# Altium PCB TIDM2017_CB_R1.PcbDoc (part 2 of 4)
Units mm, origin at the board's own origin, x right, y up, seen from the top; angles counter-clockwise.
Board outline 120 x 77 mm, 4 copper layers (Top Layer, Layer 1, Layer 2, Bottom Layer), stack 1.856 mm thick; 246 components, 167 nets, 1255 pads, 326 vias.
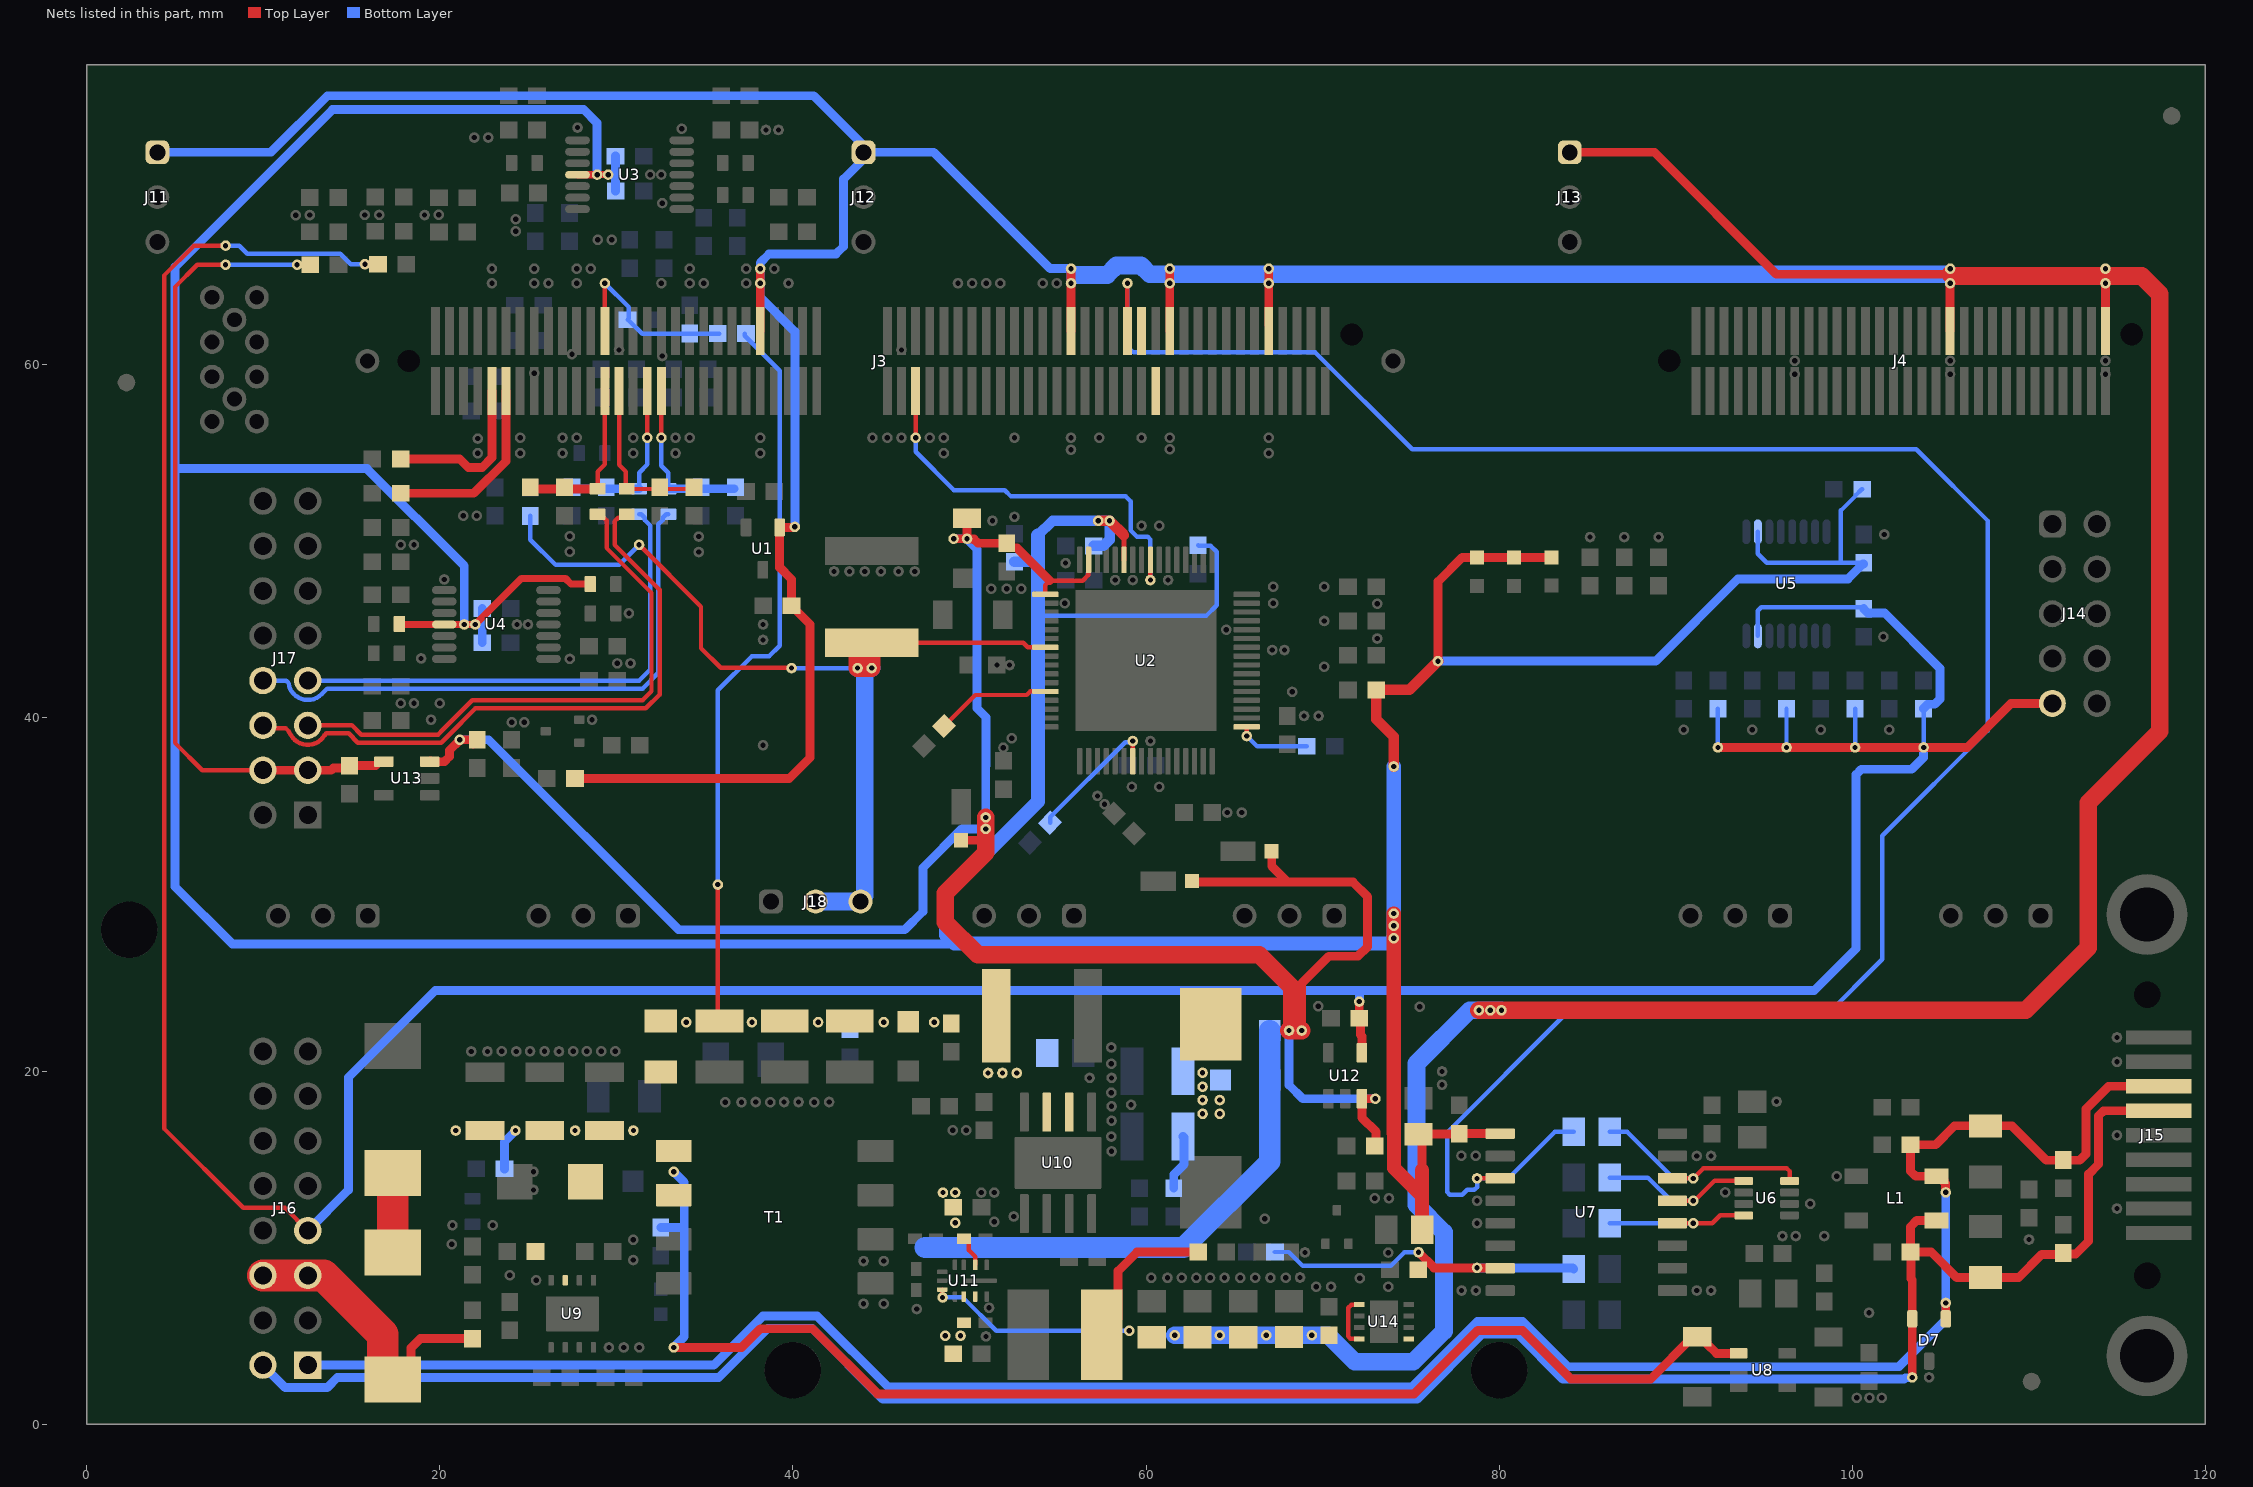
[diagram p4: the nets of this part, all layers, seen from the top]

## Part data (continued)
C24 C26 C28: library part CMP-0083626-1, "CAP, CERM, 0.1 µF, 16 V,+/- 10%, X7R, AEC-Q200 Grade 1, 0603", Cap_Case=0603, Manufacturer=AVX, Supplier Part Number 1=478-9382-1-ND, TempCo=X7R, Tolerance_%=10%, Value2=16V, ValueDisplayed=0.1µF
C29 C31: library part CMP-0007280-4, "CAP, CERM, 68 pF, 100 V, +/- 5%, C0G/NP0, 0603", Cap_Case=0603, Manufacturer=MuRata, Supplier Part Number 1=490-1347-1-ND, TempCo=C0G/NP0, Tolerance_%=5%, Value1=Unknown, Value2=100V, ValueDisplayed=68pF
C30: library part CMP-0007146-4, "CAP, CERM, 4700 pF, 50 V, +/- 10%, X7R, AEC-Q200 Grade 1, 0603", Cap_Case=0603, Manufacturer=MuRata, Supplier Part Number 1=490-4932-1-ND, TempCo=X7R, Tolerance_%=10%, Value1=Unknown, Value2=50V, ValueDisplayed=4700pF
C36 C46: library part CMP-0007255-4, "CAP, CERM, 22 pF, 100 V, +/- 5%, C0G/NP0, 0603", Cap_Case=0603, Manufacturer=MuRata, Supplier Part Number 1=490-1335-1-ND, TempCo=C0G/NP0, Tolerance_%=5%, Value1=Unknown, Value2=100V, ValueDisplayed=22pF
C37 C38 C39 C51 C52: library part CMP-0080552-1, "CAP, CERM, 22 µF, 25 V,+/- 10%, X7R, AEC-Q200 Grade 1, 1210", Cap_Case=1210, Manufacturer="Taiyo Yuden", Supplier Part Number 1=587-5949-1-ND, TempCo=X7R, Tolerance_%=10%, Value2=25V, ValueDisplayed=22µF
C40 C50 C67 C73: library part CMP-0079602-1, "CAP, CERM, 0.1 µF, 50 V,+/- 10%, X7R, AEC-Q200 Grade 1, 0603", Cap_Case=0603, Manufacturer=Kemet, Supplier Part Number 1=399-6856-1-ND, TempCo=X7R, Tolerance_%=10%, Value2=50V, ValueDisplayed=0.1µF
C41 C45: library part CMP-0007079-4, "CAP, CERM, 0.047 uF, 50 V, +/- 10%, X7R, AEC-Q200 Grade 1, 0603", Cap_Case=0603, Manufacturer=TDK, Supplier Part Number 1=445-5664-1-ND, TempCo=X7R, Tolerance_%=10%, Value1="0.049007 ohm", Value2=50V, ValueDisplayed=0.047uF
C42 C43 C44: library part CMP-0009164-2, "CAP, CERM, 10 uF, 50 V, +/- 10%, X7S, AEC-Q200 Grade 1, 1210", Cap_Case=1210_280, Manufacturer=TDK, Supplier Part Number 1=445-7004-1-ND, TempCo=X7S, Tolerance_%=10%, Value1="0.002827 ohm", Value2=50V, ValueDisplayed=10uF
C47: library part CMP-0006861-4, "CAP, CERM, 0.1 uF, 50 V, +/- 10%, X7R, 0603", Cap_Case=0603, Manufacturer=Kemet, Supplier Part Number 1=399-5089-1-ND, TempCo=X7R, Tolerance_%=10%, Value1=Unknown, Value2=50V, ValueDisplayed=0.1uF
C48: library part CMP-0008572-2, "CAP, CERM, 1000 pF, 2000 V, +/- 10%, X7R, 1206_190", Cap_Case=1206, Manufacturer="Johanson Technology", TempCo=X7R, Tolerance_%=10%, Value1=Unknown, Value2=2000V, ValueDisplayed=1000pF
C49: library part CMP-0007141-3, "CAP, CERM, 0.047 uF, 25 V, +/- 10%, X7R, AEC-Q200 Grade 1, 0603", Cap_Case=0603, Manufacturer=MuRata, Supplier Part Number 1=490-8018-1-ND, TempCo=X7R, Tolerance_%=10%, Value1=Unknown, Value2=25V, ValueDisplayed=0.047uF
C57: library part CMP-0860440-1, "CAP, CERM, 0.1 µF, 100 V,+/- 10%, X7R, AEC-Q200 Grade 1, 0805", Cap_Case=0805, Manufacturer=MuRata, TempCo=X7R, Tolerance_%=10%, Value2=100V, ValueDisplayed=0.1µF
C59 C66: library part CMP-0085644-1, "CAP, CERM, 10 µF, 16 V,+/- 20%, X6S, AEC-Q200 Grade 2, 0603", Cap_Case=0603, Manufacturer=MuRata, TempCo=X6S, Tolerance_%=20%, Value2=16V, ValueDisplayed=10µF
C60 C61 C62 C63 C72: library part CMP-0084680-1, "CAP, CERM, 22 µF, 25 V,+/- 20%, X5R, AEC-Q200 Grade 3, 0805", Cap_Case=0805, Manufacturer=MuRata, TempCo=X5R, Tolerance_%=20%, Value2=25V, ValueDisplayed=22µF
C64 C68: library part CMP-0079154-1, "CAP, CERM, 1 µF, 16 V,+/- 10%, X7R, AEC-Q200 Grade 1, 0603", Cap_Case=0603, Manufacturer=MuRata, Supplier Part Number 1=490-12657-1-ND, TempCo=X7R, Tolerance_%=10%, Value2=16V, ValueDisplayed=1µF
C65 C69 C70 C71: library part CMP-0084284-1, "CAP, CERM, 2.2 µF, 10 V,+/- 10%, X7R, AEC-Q200 Grade 1, 0603", Cap_Case=0603, Manufacturer=MuRata, TempCo=X7R, Tolerance_%=10%, Value2=10V, ValueDisplayed=2.2µF
C74 C75: library part CMP-0078265-1, "CAP, CERM, 0.22 µF, 16 V,+/- 10%, X7R, AEC-Q200 Grade 1, 0402", Cap_Case=0402, Manufacturer=MuRata, Supplier Part Number 1=490-10671-1-ND, TempCo=X7R, Tolerance_%=10%, Value2=16V, ValueDisplayed=0.22µF
C96: library part CMP-0750099-1, "CAP, CERM, 1 µF, 35 V,+/- 10%, X5R, AEC-Q200 Grade 3, 0402", Cap_Case=0402, Manufacturer=MuRata, TempCo=X5R, Tolerance_%=10%, Value2=35V, ValueDisplayed=1µF
D1 D3: library part CMP-0002905-2, "LED, Green, SMD", Color=Green, Manufacturer="Wurth Elektronik", Value1=W, Value2=3.2V
D2: library part CMP-0002947-3, "LED, Red, SMD", Color=Red, Manufacturer="Wurth Elektronik", Power_TotalModule=72mW, Value1=0.072W, Value2=2V
D4 D5 D6: library part CMP-0080709-2, "Diode, Schottky, 20 V, 2 A, AEC-Q101, PowerDI323", Manufacturer="Diodes Inc.", Value1=2A, Value2=0.47V
D7: library part CMP-0005928-2, "Diode, TVS, Bi, 7 V, SOT-23", Manufacturer=Bourns, Value1=400W
D8 D10 D13 D14: library part CMP-0085903-1, "Diode, Schottky, 60 V, 3 A, AEC-Q101, SOD-123W", Manufacturer=Nexperia, Value1=3A, Value2=0.62V
D9: library part CMP-0077075-2, "Diode, Schottky, 100 V, 3 A, AEC-Q101, SMC", Manufacturer=Vishay-Siliconix, Value1=3A, Value2=0.8V
D11: library part CMP-0005729-4, "Diode, TVS, Uni, 26 V, 42.1 Vc, AEC-Q101, SMC", Manufacturer=Littelfuse, Value1=3000W
D12: library part CMP-0005514-4, "Diode, Zener, 27 V, 3 W, SMA", Manufacturer="Micro Commercial Components", Power_W=3W
FID1 FID2 FID3: library part CMP-0077181-1, "Fiducial mark.  There is nothing to buy or mount.", Manufacturer=N/A
J1 J2: library part CMP-0055255-2, "MMCX JACK, 50 Ohm, Gold, TH", Color=Gold, Manufacturer=Molex, Supplier Part Number 1=WM5557-ND
J3: library part CMP-0003814-2, "C2000 controlCARD-120HSEC connector, SMT", Manufacturer=Samtec
J4: library part CMP-0003859-2, "C2000 controlCARD-180HSEC (60-pin addon) connector, SMT", Manufacturer=Samtec
J5 J6 J7 J8 J9 J10 J11 J12 J13 J18: library part CMP-0076709-1, "Receptacle, 2.54mm, 3x1, Gold, TH", Color=Black, Manufacturer=Mill-Max, Supplier Part Number 1=575-8014100310001000
J14: library part CMP-0860034-1, "Header, 2.54mm, 5x2, Gold, TH", Color=Black, Manufacturer=Samtec
J15: library part CMP-0074875-1, "Receptacle, D-Sub, 9 Position, R/A, SMT", Color=Black, Manufacturer=NorComp, Supplier Part Number 1=190-09FA-ND
J16 J17: library part CMP-0075673-1, "Header (Shrouded), 2.54mm, 8x2, Tin, R/A, TH", Color=Black, Manufacturer=Samtec, Supplier Part Number 1=TSS-108-04-L-D-RA-ND
L1: library part CMP-0076845-1, "Coupled inductor, 51 µH, 0.2 A, 1 ohm, AEC-Q200 Grade 0, SMD", Manufacturer=TDK, Supplier Part Number 1=445-3958-1-ND, ValueDisplayed=51µH
L2: library part CMP-0079799-1, "Inductor, Shielded, 68 µH, 2 A, 0.24 ohm, AEC-Q200 Grade 1, SMD", Manufacturer="Pulse Engineering", Supplier Part Number 1=553-3443-1-ND, Value1="0.24 ohm", Value2=2A, ValueDisplayed=68µH
L3: library part CMP-0056765-1, "Inductor, Shielded, Ferrite, 10 uH, 3.2 A, 0.0624 ohm, AEC-Q200 Grade 1, SMD", Manufacturer=Bourns, Supplier Part Number 1=SRN6045TA-100MCT-ND, Value1="0.0624 ohm", Value2=3.2A, ValueDisplayed=10uH
LBL1: library part CMP-0003625-1, "Thermal Transfer Printable Labels, 0.650\" W x 0.200\" H - 10,000 per roll", Manufacturer=Brady, Supplier Part Number 1=97C5133
Logo1: library part CMP-0074838-1, "Texas Instrument Corporate Signature"
Logo2: library part CMP-0074844-1
Logo3: library part CMP-0074847-1, "FCC_disclaimer"
Logo4: library part CMP-0074769-1
Q1 Q2: library part CMP-0000791-1, "MOSFET, N-CH, 60 V, 0.28 A, AEC-Q101, SOT-323", Alternate Manufacturer=None, Manufacturer="Infineon Technologies", Supplier Part Number 1=BSS138WH6327XTSA1CT-ND, Value2="1 nC"
R1 R4: library part CMP-0081280-1, "RES, 47.0, 1%, 0.1 W, AEC-Q200 Grade 0, 0603", Manufacturer=Vishay-Dale, Power_W=100mW, Supplier Part Number 1=541-47.0HCT-ND, TempCo="100 ppm/C", Tolerance_%=1%, Value2=0.1W, Value_Code=47R0, ValueDisplayed=47.0
R2 R5: library part CMP-0022455-4, "RES, 4.64 k, 1%, 0.1 W, AEC-Q200 Grade 0, 0603", Manufacturer=Vishay-Dale, Power_W=100mW, Supplier Part Number 1=541-4.64KHCT-ND, TempCo="100 ppm/C", Tolerance_%=1%, Value2=0.1W, Value_Code=4k64, ValueDisplayed=4.64k
R3: library part CMP-0022115-4, "RES, 1.15 k, 1%, 0.1 W, AEC-Q200 Grade 0, 0603", Manufacturer=Vishay-Dale, Power_W=100mW, Supplier Part Number 1=541-1.15KHCT-ND, TempCo="100 ppm/C", Tolerance_%=1%, Value2=0.1W, Value_Code=1k15, ValueDisplayed=1.15k
R6 R9 R15 R30 R31 R67 R81: library part CMP-0023168-5, "RES, 51.1, 1%, 0.1 W, 0603", Manufacturer=Yageo, Power_W=100mW, Supplier Part Number 1=311-51.1HRCT-ND, TempCo="100 ppm/C", Tolerance_%=1%, Value2=0.1W, Value_Code=51R1, ValueDisplayed=51.1
R7 R12 R70 R72: library part CMP-0023837-2, "RES, 18.4 k, 0.1%, 0.1 W, 0603", Manufacturer="Yageo America", Power_W=100mW, TempCo="25 ppm/C", Tolerance_%=0.1%, Value2=0.1W, Value_Code=18k4, ValueDisplayed=18.4k
R8 R29 R32 R56 R66 R69 R71 R73 R76 R78 R82 R84 R86 R87: library part CMP-0022746-5, "RES, 10.0 k, 1%, 0.1 W, 0603", Manufacturer=Yageo, Power_W=100mW, Supplier Part Number 1=311-10.0KHRCT-ND, TempCo="100 ppm/C", Tolerance_%=1%, Value2=0.1W, Value_Code=10k0, ValueDisplayed=10.0k
R10: library part CMP-0025288-2, "RES, 43.7 k, 0.5%, 0.1 W, 0603", Manufacturer="Yageo America", Power_W=100mW, TempCo="50 ppm/C", Tolerance_%=0.5%, Value2=0.1W, Value_Code=43k7, ValueDisplayed=43.7k
R11: library part CMP-0021998-4, "RES, 10.0 k, 1%, 0.1 W, AEC-Q200 Grade 0, 0603", Manufacturer=Vishay-Dale, Power_W=100mW, Supplier Part Number 1=541-10.0KHCT-ND, TempCo="100 ppm/C", Tolerance_%=1%, Value2=0.1W, Value_Code=10k0, ValueDisplayed=10.0k
R13 R28 R39 R55 R68 R74 R75 R77 R79 R80 R83 R85: library part CMP-0088378-2, "6.04 kOhms ±0.1% 0.2W, 1/5W Chip Resistor 0603 (1608 Metric) Automotive AEC-Q200, Pulse Withstanding Thick Film", Digikey Part Number=P20061CT-ND, Manufacturer=Panasonic, Mouser Part Number=667-ERJ-PB3B6041V, Operating Temperature Range="-55°C to +155°C", Power_W=200mW, TempCo=50ppm/°C, Tolerance_%=0.1%
R14 R19 R20 R38 R57: library part CMP-0023385-3, "RES, 100 k, 0.05%, 0.1 W, AEC-Q200 Grade 0, 0603", Manufacturer=Panasonic, Power_W=100mW, Supplier Part Number 1=P100KBECT-ND, TempCo="10 ppm/C", Tolerance_%=0.05%, Value2=0.1W, Value_Code=100k
R16 R17 R18: library part CMP-0024021-2, "RES, 271, 0.1%, 0.1 W, 0603", Manufacturer="Yageo America", Power_W=100mW, TempCo="25 ppm/C", Tolerance_%=0.1%, Value2=0.1W, Value_Code=271R, ValueDisplayed=271
R21 R22 R63 R65: library part CMP-0023341-3, "RES, 10.0 k, 1%, 0.1 W, AEC-Q200 Grade 0, 0603", Manufacturer="Stackpole Electronics Inc", Power_W=100mW, Supplier Part Number 1=RMCF0603FT10K0CT-ND, TempCo="100 ppm/C", Tolerance_%=1%, Value2=0.1W, Value_Code=10k0, ValueDisplayed=10.0k
R23 R24 R25 R26 R27 R62 R64 R88: library part CMP-0022109-5, "RES, 1.00 k, 1%, 0.1 W, AEC-Q200 Grade 0, 0603", Manufacturer=Vishay-Dale, Power_W=100mW, Supplier Part Number 1=541-1.00KHCT-ND, TempCo="100 ppm/C", Tolerance_%=1%, Value2=0.1W, Value_Code=1k00, ValueDisplayed=1.00k
R33: library part CMP-0023343-3, "RES, 0, 1%, 0.1 W, AEC-Q200 Grade 0, 0603", Manufacturer="Stackpole Electronics Inc", Power_W=100mW, Supplier Part Number 1=RMCF0603ZT0R00CT-ND, TempCo=ppm/C, Tolerance_%=1%, Value2=0.1W, Value_Code=0
R34 R37 R40: library part CMP-0086358-1, "RES, 0, 0%, 0.25 W, AEC-Q200 Grade 0, 0603", Manufacturer=Rohm, Power_W=250mW, Tolerance_%=0%, Value2=0.25W, Value_Code=0000, ValueDisplayed=0
R35 R36: library part CMP-0018709-3, "RES, 60, 10%, 0.25 W, AEC-Q200 Grade 0, 1206", Manufacturer=Vishay-Dale, Power_W=250mW, Supplier Part Number 1=CRCW120660R0KNEAIF-ND, TempCo="200 ppm/C", Tolerance_%=10%, Value2=0.25W, Value_Code=60R0, ValueDisplayed=60
R41 R42 R43 R44 R45: library part CMP-0020443-3, "RES, 0, 5%, 0.333 W, AEC-Q200 Grade 0, 0805", Manufacturer=Vishay-Dale, Power_W=333mW, Supplier Part Number 1=541-0.0TBCT-ND, TempCo="200 ppm/C", Tolerance_%=5%, Value2=0.333W, Value_Code=0000, ValueDisplayed=0
R46: library part CMP-0084243-1, "RES, 100, 1%, 0.25 W, AEC-Q200 Grade 0, 0603", Manufacturer=Vishay-Dale, Power_W=250mW, TempCo="100 ppm/C", Tolerance_%=1%, Value2=0.25W, Value_Code=100R, ValueDisplayed=100
R47: library part CMP-0021991-4, "RES, 100, 1%, 0.1 W, AEC-Q200 Grade 0, 0603", Manufacturer=Vishay-Dale, Power_W=100mW, Supplier Part Number 1=541-100HCT-ND, TempCo="100 ppm/C", Tolerance_%=1%, Value2=0.1W, Value_Code=100R, ValueDisplayed=100
R48 R52: library part CMP-0018760-2, "RES, 0, 5%, 0.25 W, AEC-Q200 Grade 0, 1206", Manufacturer=Vishay-Dale, Power_W=250mW, Supplier Part Number 1=541-2239-1-ND, TempCo=ppm/C, Tolerance_%=5%, Value2=0.25W, Value_Code=0000, ValueDisplayed=0
R49 R50: library part CMP-0022244-4, "RES, 261 k, 1%, 0.1 W, AEC-Q200 Grade 0, 0603", Manufacturer=Vishay-Dale, Power_W=100mW, Supplier Part Number 1=541-261KHCT-ND, TempCo="100 ppm/C", Tolerance_%=1%, Value2=0.1W, Value_Code=261k
R51: library part CMP-0022024-4, "RES, 121 k, 1%, 0.1 W, AEC-Q200 Grade 0, 0603", Manufacturer=Vishay-Dale, Power_W=100mW, Supplier Part Number 1=541-121KHCT-ND, TempCo="100 ppm/C", Tolerance_%=1%, Value2=0.1W, Value_Code=121k
R53: library part CMP-0022030-4, "RES, 12.1 k, 1%, 0.1 W, AEC-Q200 Grade 0, 0603", Manufacturer=Vishay-Dale, Power_W=100mW, Supplier Part Number 1=541-12.1KHCT-ND, TempCo="100 ppm/C", Tolerance_%=1%, Value2=0.1W, Value_Code=12k1, ValueDisplayed=12.1k
R54: library part CMP-0022544-4, "RES, 64.9 k, 1%, 0.1 W, AEC-Q200 Grade 0, 0603", Manufacturer=Vishay-Dale, Power_W=100mW, Supplier Part Number 1=541-64.9KHCT-ND, TempCo="100 ppm/C", Tolerance_%=1%, Value2=0.1W, Value_Code=64k9, ValueDisplayed=64.9k
R58: library part CMP-0031885-1, "97.6 kOhms ±0.5% 0.2W, 1/5W Chip Resistor 0603 (1608 Metric) Automotive AEC-Q200, Pulse Withstanding Thick Film", Digikey Part Number=P20510CT-ND, Manufacturer=Panasonic, Mouser Part Number=667-ERJ-PB3D9762V, Operating Temperature Range="-55°C to +155°C", Power_W=200mW, TempCo=50ppm/°C, Tolerance_%=0.5%
R59: library part CMP-0022665-4, "RES, 9.09 k, 1%, 0.1 W, AEC-Q200 Grade 0, 0603", Manufacturer=Vishay-Dale, Power_W=100mW, Supplier Part Number 1=541-9.09KHCT-ND, TempCo="100 ppm/C", Tolerance_%=1%, Value2=0.1W, Value_Code=9k09, ValueDisplayed=9.09k
T1: library part CMP-0088070-1, "FLYBACK TRANSFORMER", Manufacturer=Coilcraft
U1: library part CMP-0079649-1, "Automotive 20 ppm / degC Max, 100 uA, SOT23-3 Series Voltage Reference, DBZ0003A (SOT-23-3)", Alternate Manufacturer="Texas Instruments", Alternate PartNumber=REF3133AQDBZTQ1
U2: library part CMP-0089128-1, "3-Phase 48-V Automotive Gate Driver Unit (GDU) with Advanced Protection and Diagnostics", Manufacturer="Texas Instruments", Max Supply Voltage=15V, Min Supply Voltage=3V, Nominal Supply Current=15-24mA, Operating Temperature Range="-40°C to +175°C"
U3 U4: library part CMP-0082283-1, "4 channel, 10-MHz, Low-Noise, RRIO, CMOS Operational Amplifier for Cost-Sensitive Systems, PW0014A (TSSOP-14)", Alternate Manufacturer="Texas Instruments", Alternate PartNumber=TLV9064IPWT, Operating Temperature Range="-40 to 125 C", Rating=Catalog
U5: library part CMP-0067443-1, "6-Bit Bidirectional Voltage-Level Translator with Auto Direction Sensing and +/-15-kV ESD Protect, PW0016A (TSSOP-16)", Alternate Manufacturer="Texas Instruments"
U6: library part CMP-0089901-1, "Automotive High Speed CAN Transceiver", Manufacturer="Texas Instruments", Max Supply Voltage=5.5V, Min Supply Voltage=4.5V, Nominal Supply Current=5-180mA, Operating Temperature Range="-40°C to +150°C"
U7: library part CMP-0078446-2, "High Speed, Robust EMC Triple-Channel Digital Isolators, DW0016B (SOIC-16)", Alternate Manufacturer="Texas Instruments", Alternate PartNumber=ISO7731DW, Operating Temperature Range="-55 to 125 C", Rating=Catalog
U8: library part CMP-0077329-2, "Automotive High-Voltage Ultra-Low IQ Low-Dropout Regulator/Fixed 5-V Output Voltage, DBV0005A (SOT-23-5)", Alternate Manufacturer="Texas Instruments"
U9: library part CMP-0860959-2, "42-VIN PSR Flyback DC/DC Converter with 65-V, 4-A Integrated MOSFET, NGU0008C (WSON-8)", Alternate Manufacturer="Texas Instruments"
U10: library part CMP-0097344-1, "4.2-V to 80-V, 1-A Synchronous Buck Converter with 40-µA IQ", Manufacturer="Texas Instruments", Max Supply Voltage=80V, Min Supply Voltage=4.2V, Nominal Supply Current=40uA, Operating Temperature Range="-40°C to +150°C", Output Voltage=1-75V, Switching Frequency=200-2200kHz
U11: library part CMP-0860362-1, "3.8-V to 36-V, 2-A Synchronous step-down voltage converter, RNX0012B (VQFN-HR-12)", Alternate Manufacturer="Texas Instruments", Alternate PartNumber=LMR33620AQ5RNXTQ1, Operating Temperature Range="-40 to 125 C", Rating=Automotive
U12 U13: library part CMP-0096536-1, "Automotive, 70-mA, 40-V, Voltage-Tracking LDO With 5-mV Tracking Tolerance, SOT23-5", Dropout Voltage=500mV, Manufacturer="Texas Instruments", Max Supply Voltage=40V, Min Supply Voltage=3V, Nominal Supply Current=600-800uA, Operating Temperature Range="-40°C to +125°C", Output Voltage=2-40V
U14: library part CMP-0096433-1, "Automotive, 500-mA, Low-Noise, Low-IQ, High-PSRR LDO", Dropout Voltage=750mV, Manufacturer="Texas Instruments", Max Supply Voltage=6V, Min Supply Voltage=2V, Nominal Supply Current=6.5uA, Operating Temperature Range="-40°C to +150°C", Output Voltage=0.8-5.5V
ZZ1: library part CMP-0003616-3
ZZ2: library part CMP-0077236-1
ZZ3: library part CMP-0077237-1
ZZ4: library part CMP-0077238-1

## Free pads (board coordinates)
  round 0.6 hole 0.3: 2(7.864,65.671) 2(7.864,66.756) 2(11.837,68.472) 2(11.914,65.671) 2(12.638,68.487) 2(15.75,68.494) 2(15.76,65.705) 2(16.572,68.494) 2(17.782,40.829) 2(17.782,49.804) 2(18.532,40.829) 2(18.532,49.804) 2(18.938,43.369) 2(19.137,68.487) 2(19.5,39.897) 2(19.937,68.501) 2(20,40.829) 2(20.255,47.844) 2(20.678,10.192) 2(20.713,11.267) 2(20.902,16.631) 2(21.127,38.767) 2(21.331,51.45) 2(21.383,45.294) 2(21.778,21.108) 2(21.956,72.877) 2(22.005,45.294) 2(22.088,51.45) 2(22.15,55.825) 2(22.15,55) 2(22.697,21.108) 2(22.744,72.877) 2(22.95,64.625) 2(22.95,65.45) 2(22.992,11.267) 2(23.501,21.12) 2(23.966,8.436) 2(24.073,39.75) 2(24.282,16.631) 2(24.297,67.568) 2(24.297,68.25) 2(24.335,21.108) 2(24.371,45.294) 2(24.55,55) 2(24.55,55.875) 2(24.781,39.75) 2(24.992,45.294) 2(25.111,21.12) 2(25.305,13.265) 2(25.305,14.302) 2(25.35,59.531) 2(25.35,64.625) 2(25.35,65.45) 2(25.454,8.146) 2(25.932,21.12) 2(26.15,64.625) 2(26.75,21.109) 2(26.95,55) 2(26.95,55.875) 2(27.364,43.344) 2(27.364,49.421) 2(27.364,50.296) 2(27.481,60.608) 2(27.552,21.12) 2(27.662,16.631) 2(27.75,55.875) 2(27.75,64.625) 2(27.75,65.45) 2(27.799,73.44) 2(28.322,21.12) 2(28.55,65.45) 2(28.623,39.897) 2(28.911,70.776) 2(28.948,67.081) 2(29.14,21.12) 2(29.35,64.625) 2(29.532,70.776) 2(29.577,4.342) 2(29.738,67.081) 2(29.942,21.12) 2(30.05,43.091) 2(30.151,60.847) 2(30.424,4.342) 2(30.711,45.925) 2(30.8,43.091) 2(30.95,55) 2(30.95,55.875) 2(30.954,9.295) 2(30.954,10.438) 2(30.966,16.631) 2(31.287,49.804) 2(31.295,4.346) 2(31.75,55.875) 2(31.92,70.776) 2(32.541,70.776) 2(32.55,55.875) 2(32.55,64.625) 2(32.602,60.498) 2(32.602,69.163) 2(33.249,4.346) 2(33.249,14.293) 2(33.35,55) 2(33.35,55.875) 2(33.699,73.375) 2(33.958,22.769) 2(34.15,55.875) 2(34.15,64.625) 2(34.15,65.45) 2(34.666,49.4) 2(34.666,50.275) 2(34.95,64.625) 2(35.75,30.56) 2(36.166,18.234) 2(37.085,18.234) 2(37.35,64.625) 2(37.35,65.45) 2(37.678,22.769) 2(37.89,18.246) 2(38.15,55) 2(38.15,55.875) 2(38.15,64.625) 2(38.15,65.45) 2(38.308,38.45) 2(38.308,44.419) 2(38.308,45.294) 2(38.475,73.305) 2(38.723,18.234) 2(38.95,65.45) 2(39.183,73.305) 2(39.499,18.246) 2(39.75,64.625) 2(39.922,42.825) 2(40.11,50.823) 2(40.32,18.246) 2(41.209,18.234) 2(41.428,22.769) 2(42.05,18.246) 2(42.331,48.3) 2(43.201,48.3) 2(43.662,42.825) 2(44,6.821) 2(44,9.237) 2(44.068,48.3) 2(44.458,42.825) 2(44.502,55.875) 2(44.985,48.3) 2(45.15,6.821) 2(45.15,9.237) 2(45.15,22.769) 2(45.35,55.875) 2(45.983,48.3) 2(46.15,55.875) 2(46.15,60.847) 2(46.901,48.3) 2(46.95,55.875) 2(47.012,6.519) 2(47.75,55.875) 2(48,22.769) 2(48.478,7.174) 2(48.497,13.115) 2(48.55,55) 2(48.55,55.875) 2(48.626,5.003) 2(49.058,16.646) 2(49.102,50.148) 2(49.194,13.115) 2(49.194,11.4) 2(49.35,64.625) 2(49.495,5.003) 2(49.813,16.646) 2(49.862,50.148) 2(50.15,64.625) 2(50.665,13.115) 2(50.917,33.714) 2(50.917,34.366) 2(50.936,4.967) 2(50.95,64.625) 2(51.055,19.889) 2(51.108,6.586) 2(51.229,47.319) 2(51.305,51.17) 2(51.402,11.458) 2(51.402,13.115) 2(51.562,43) 2(51.75,64.625) 2(51.868,19.889) 2(51.922,38.317) 2(52.106,47.319) 2(52.273,42.999) 2(52.397,38.853) 2(52.51,11.761) 2(52.55,51.389) 2(52.55,55.875) 2(52.681,19.889) 2(52.931,47.319) 2(54.15,64.625) 2(54.95,64.625) 2(55.402,46.5) 2(55.446,48.773) 2(55.75,55.194) 2(55.75,55.875) 2(55.754,64.625) 2(55.754,65.45) 2(56.804,19.61) 2(57.25,35.583) 2(57.3,51.174) 2(57.35,55.875) 2(57.654,35.112) 2(57.936,51.174) 2(58.038,16.29) 2(58.038,18.777) 2(58.038,20.414) 2(58.038,21.334) 2(58.05,15.449) 2(58.05,17.179) 2(58.05,18) 2(58.05,19.61) 2(58.25,47.811) 2(58.95,64.625) 2(59.049,5.29) 2(59.155,18.084) 2(59.2,36.095) 2(59.25,38.692) 2(59.25,47.811) 2(59.75,55.875) 2(59.75,50.884) 2(60.25,38.692) 2(60.25,47.811) 2(60.297,8.284) 2(60.75,36.095) 2(60.75,50.884) 2(61.217,8.284) 2(61.25,47.811) 2(61.35,55.219) 2(61.35,55.875) 2(61.35,64.625) 2(61.35,65.45) 2(61.63,5.034) 2(62.021,8.296) 2(62.854,8.284) 2(63.205,17.574) 2(63.205,18.357) 2(63.205,19.111) 2(63.205,19.9) 2(63.631,8.296) 2(64.182,5.03) 2(64.182,17.574) 2(64.182,18.357) 2(64.452,8.296) 2(64.55,45) 2(64.604,34.642) 2(65.341,8.284) 2(65.43,34.642) 2(65.708,38.975) 2(66.182,8.296) 2(66.724,11.632) 2(66.81,5.034) 2(66.95,55) 2(66.95,55.875) 2(66.95,64.625) 2(66.95,65.45) 2(67.049,8.293) 2(67.145,43.848) 2(67.202,47.434) 2(67.202,46.5) 2(67.845,43.848) 2(67.922,8.293) 2(68.103,22.294) 2(68.279,41.477) 2(68.727,8.305) 2(68.823,22.294) 2(68.95,40.111) 2(69.004,9.722) 2(69.396,5.034) 2(69.636,7.784) 2(69.758,23.676) 2(69.776,40.111) 2(70.091,42.905) 2(70.091,45.493) 2(70.091,47.434) 2(70.482,7.786) 2(72.082,23.935) 2(72.114,8.269) 2(72.957,12.792) 2(72.991,18.435) 2(73.102,44.5) 2(73.102,46.473) 2(73.717,9.715) 2(73.728,7.784) 2(73.763,12.792) 2(74.031,37.25) 2(74.031,27.52) 2(74.031,28.228) 2(74.031,28.918) 2(75.437,9.736) 2(75.501,23.644) 2(76.538,43.219) 2(76.767,19.223) 2(76.769,19.975) 2(77.864,15.199) 2(77.876,7.568) 2(78.675,15.199) 2(78.687,7.568) 2(78.75,8.85) 2(78.75,11.378) 2(78.75,12.648) 2(78.75,13.918) 2(78.86,23.437) 2(79.506,23.437) 2(80.135,23.437) 2(85.151,50.247) 2(87.091,50.247) 2(89.035,50.247) 2(90.456,39.329) 2(90.999,11.378) 2(90.999,12.648) 2(90.999,13.918) 2(91.195,7.568) 2(91.195,15.188) 2(92.006,7.568) 2(92.006,15.188) 2(92.397,38.329) 2(92.806,13.127) 2(94.339,39.329) 2(95.716,18.271) 2(96.052,10.653) 2(96.28,38.329) 2(96.748,59.472) 2(96.748,60.228) 2(96.802,10.653) 2(97.619,12.477) 2(98.222,39.329) 2(98.418,10.653) 2(99.13,14.04) 2(100.163,38.329) 2(100.264,1.486) 2(100.955,6.31) 2(100.981,1.486) 2(101.68,1.486) 2(101.768,44.595) 2(101.823,50.395) 2(102.105,39.329) 2(103.405,2.646) 2(104.046,38.329) 2(104.355,2.646) 2(105.305,13.127) 2(105.305,6.864) 2(105.548,59.472) 2(105.548,60.228) 2(105.548,64.625) 2(105.548,65.45) 2(110.016,10.456) 2(114.348,59.472) 2(114.348,60.228) 2(114.348,64.625) 2(114.348,65.45) 2(115,12.212) 2(115,16.365) 2(115,20.518) 2(115,21.902)
  round 3.2 hole 3.2 unplated: 3(2.4,28) 3(40,3.059) 3(80,3.059)

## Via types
v1: diameter 0.6, hole 0.3, Top Layer to Bottom Layer, 276 vias
v2: diameter 0.5, hole 0.2, Top Layer to Bottom Layer, 40 vias
v3: diameter 0.63, hole 0.33, Top Layer to Bottom Layer, tented both sides, 6 vias
v4: diameter 0.5, hole 0.2, Top Layer to Bottom Layer, tented both sides, 4 vias

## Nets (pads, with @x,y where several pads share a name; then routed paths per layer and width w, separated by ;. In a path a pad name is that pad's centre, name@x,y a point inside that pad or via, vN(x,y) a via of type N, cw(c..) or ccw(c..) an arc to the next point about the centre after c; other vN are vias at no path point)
5V_POS: C16.2 C69.1 J14.9 J16.7 pad.2@7.864,66.756 pad.2@15.76,65.705 pad.2@72.082,23.935 pad.2@92.397,38.329 pad.2@96.28,38.329 pad.2@100.163,38.329 pad.2@104.046,38.329 R23.2 R24.2 R25.2 R27.2 R70.1 U5.15 U12.4 | length 233.4
  Top Layer w0.254: pad.2@7.864,66.756 6.074,66.756 4.38,65.062 4.38,16.74 8.87,12.25 11.23,12.25 J16.7@12.52,10.96 ; pad.2@15.76,65.705 R70.1@16.572,65.705
  Top Layer w0.5: pad.2@72.082,23.935 C69.1@72.082,22.985 72.144,22.923 72.144,22.053 72.232,21.965 U12.4@72.232,21.035 ; pad.2@92.397,38.329 pad.2@96.28,38.329 pad.2@100.163,38.329 pad.2@104.046,38.329 106.512,38.329 109.006,40.823 J14.9@111.335,40.823
  Bottom Layer w0.254: pad.2@7.864,66.756 8.634,66.756 9.091,66.298 14.367,66.298 14.961,65.705 pad.2@15.76,65.705 ; pad.2@92.397,38.329 R27.2@92.397,40.522 ; U5.15@94.655,44.645 94.655,46.067 94.859,46.27 100.582,46.27 C16.2@100.657,46.195 ; pad.2@96.28,38.329 R23.2@96.28,40.522 ; pad.2@100.163,38.329 R24.2@100.163,40.522 ; pad.2@104.046,38.329 R25.2@104.046,40.522
  Bottom Layer w0.5: J16.7@12.52,10.96 14.825,13.265 14.825,19.647 19.739,24.561 72.094,24.561 ; pad.2@72.082,23.935 72.094,23.947 72.094,24.561 ; C16.2@100.657,46.195 100.657,46.17 100.882,45.945 101.835,45.945 104.971,42.809 104.971,41.065 104.678,40.772 104.271,40.772 104.046,40.547 R25.2@104.046,40.522 ; pad.2@104.046,38.329 104.046,37.765 103.371,37.09 100.517,37.09 100.224,36.797 100.224,26.94 97.844,24.561 72.094,24.561
5V_THROTTLE: C65.1 J17.3 J17.4 pad.2@7.864,65.671 pad.2@11.914,65.671 R72.1 U13.4 | length 46.8
  Top Layer w0.254: pad.2@7.864,65.671 6.261,65.671 5,64.41 5,38.584 6.544,37.04 J17.4@9.98,37.04 ; pad.2@11.914,65.671 R72.1@12.737,65.671
  Top Layer w0.5: J17.4@9.98,37.04 J17.3@12.52,37.04 13.85,37.04 13.98,37.171 14.758,37.171 C65.1@14.887,37.3 16.354,37.3 16.577,37.523 U13.4@16.827,37.523
  Bottom Layer w0.254: pad.2@7.864,65.671 pad.2@11.914,65.671
12V_BAT_SENSE: C95.2 J3.26 pad.2@29.35,64.625 R10.2 R87.2 | length 10.9
  Top Layer w0.254: J3.26@29.35,61.919 pad.2@29.35,64.625
  Bottom Layer w0.254: pad.2@29.35,64.625 30.711,63.264 30.711,62.636 R87.2@30.632,62.557 30.657,62.557 31.459,61.755 32.868,61.755 32.888,61.775 C95.2@34.15,61.775 R10.2@35.819,61.775
+3.3V: C15.1 C23.1 C24.1 C71.1 C72.1 C76.1 C87.2 C88.1 C92.2 C93.1 D1.2 D2.2 D3.2 pad.2@21.383,45.294 pad.2@22.005,45.294 pad.2@28.911,70.776 pad.2@29.532,70.776 pad.2@57.3,51.174 pad.2@57.936,51.174 pad.2@74.031,27.52 pad.2@74.031,28.228 pad.2@74.031,28.918 pad.2@74.031,37.25 pad.2@75.437,9.736 pad.2@76.538,43.219 pad.2@78.75,8.85 R11.2 R21.1 R22.1 R26.1 R41.1 R75.1 R80.1 R88.1 U2.11 U3.4 U4.4 U5.2 U7.1 U7.7 U14.1 | length 344.2
  Top Layer w0.254: R75.1@17.734,45.294 R75.1@17.734,45.419
  Top Layer w0.3: U2.11@58.75,48.95 58.75,50.36
  Top Layer w0.4: R75.1@17.734,45.294 U4.4@20.255,45.294 pad.2@21.383,45.294 pad.2@22.005,45.294 24.621,47.911 27.105,47.911 27.432,47.583 R80.1@28.525,47.583 ; U3.4@27.799,70.77 pad.2@28.905,70.77 ; pad.2@28.911,70.776 pad.2@29.532,70.776
  Top Layer w0.5: pad.2@28.905,70.77 pad.2@28.911,70.776 ; C71.1@75.424,8.744 C71.1@75.471,8.791 ; pad.2@75.437,9.736 76.322,8.85 pad.2@78.75,8.85 78.756,8.844 80.06,8.844 U7.7@80.066,8.838 ; 75.64,14.381 75.64,16.22 C23.1@75.432,16.428 75.445,16.442 C24.1@77.736,16.442 ; pad.2@76.538,43.219 76.538,47.722 77.911,49.095 D1.2@82.959,49.095 ; C24.1@77.751,16.456 80.064,16.456 U7.1@80.066,16.458
  Top Layer w0.6: pad.2@57.3,51.174 pad.2@57.936,51.174 58.75,50.36 ; pad.2@74.031,37.25 74.031,38.932 73.039,39.924 R22.1@73.039,41.587 74.906,41.587 pad.2@76.538,43.219
  Top Layer w0.8: pad.2@74.031,27.371 74.031,16.497 74.057,16.47 74.057,14.506 75.64,12.923 ; pad.2@74.031,27.52 pad.2@74.031,28.228 pad.2@74.031,28.918 ; C72.1@75.64,11.008 75.64,12.923 ; 75.64,14.381 75.64,12.923
  Bottom Layer w0.254: 53.878,45.777 63.402,45.777 64,46.375 64,49.419 63.675,49.744 62.979,49.744 R11.2@62.95,49.773 ; R88.1@67.305,9.75 68.089,9.75 68.88,8.959 73.861,8.959 74.638,9.736 pad.2@75.437,9.736 ; U5.2@94.655,50.545 94.655,49.305 95.166,48.795 99.364,48.795 ; R26.1@100.561,52.949 100.536,52.949 100.188,52.601 100.188,52.576 99.364,51.752 99.364,48.795 ; C15.1@100.582,48.795 99.364,48.795 ; C15.1@100.657,48.72 C15.1@100.657,48.795
  Bottom Layer w0.4: pad.2@21.383,45.294 pad.2@22.005,45.294 22.339,45.294 22.407,45.226 ; C87.2@22.405,44.254 C87.2@22.407,44.257 ; C88.1@22.407,46.195 C88.1@22.41,46.197 ; pad.2@28.911,70.776 29.892,70.776 29.954,70.838
  Bottom Layer w0.5: pad.2@21.383,45.294 21.383,48.611 15.869,54.125 5,54.125 ; C87.2@22.407,44.257 22.407,45.226 ; 22.407,45.294 C88.1@22.407,46.195 ; pad.2@28.911,70.776 28.911,73.696 28.143,74.465 13.929,74.465 5,65.535 5,54.125 ; C93.1@29.949,71.823 29.954,71.818 29.954,70.838 29.954,69.859 C92.2@29.96,69.854 ; 49.145,27.204 8.24,27.204 5,30.444 5,54.125 ; pad.2@76.538,43.219 88.874,43.219 93.53,47.875 99.762,47.875 100.607,48.72 C15.1@100.657,48.72 ; pad.2@78.777,8.85 84.172,8.85 R41.1@84.234,8.788
  Bottom Layer w0.6: R21.1@52.55,48.842 53.765,48.842 53.878,48.729 ; 53.878,50.342 54.71,51.174 pad.2@57.3,51.174 pad.2@57.936,51.174 57.936,50.095 57.585,49.744 C76.1@57.046,49.744
  Bottom Layer w0.8: 53.878,50.342 53.878,48.729 53.878,45.777 53.878,35.272 48.676,30.071 48.676,27.696 49.145,27.227 73.737,27.227 pad.2@74.031,27.52 pad.2@74.031,28.228 pad.2@74.031,28.769 ; pad.2@74.031,28.918 pad.2@74.031,28.769 ; pad.2@74.031,37.25 pad.2@74.031,28.769
+5V: C1.1 C60.1 C61.1 C62.1 C63.1 C70.1 J3.48 J3.84 J3.98 J3.112 J4.158 J4.180 J11.1 J12.1 J13.1 L3.2 pad.2@38.15,64.625 pad.2@38.15,65.45 pad.2@40.11,50.823 pad.2@48.478,7.174 pad.2@55.754,64.625 pad.2@55.754,65.45 pad.2@59.049,5.29 pad.2@61.35,64.625 pad.2@61.35,65.45 pad.2@61.63,5.034 pad.2@64.182,5.03 pad.2@66.81,5.034 pad.2@66.95,64.625 pad.2@66.95,65.45 pad.2@69.396,5.034 pad.2@78.86,23.437 pad.2@79.506,23.437 pad.2@80.135,23.437 pad.2@105.548,64.625 pad.2@105.548,65.45 pad.2@114.348,64.625 pad.2@114.348,65.45 R62.1 R64.1 U1.1 U11.7 U14.5 U14.8 | length 357.4
  Top Layer w0.254: U11.7@48.452,7.621 48.463,7.621 48.465,7.619 48.465,7.187 pad.2@48.478,7.174 ; U14.8@72.081,4.824 72.058,4.847 71.574,4.847 71.454,4.967 71.454,6.586 71.619,6.751 72.058,6.751 U14.5@72.081,6.774
  Top Layer w0.5: R62.1@27.653,36.573 39.797,36.573 40.966,37.742 40.966,45.307 40.172,46.101 40.172,46.126 39.947,46.351 C1.1@39.922,46.351 39.922,47.849 39.244,48.526 U1.1@39.244,50.789 40.05,50.789 40.083,50.823 pad.2@40.11,50.823 ; J3.48@38.15,61.919 38.15,63.793 pad.2@38.15,64.625 pad.2@38.15,65.45 ; J3.84@55.75,61.919 55.75,63.793 55.754,63.796 pad.2@55.754,64.625 pad.2@55.754,65.45 ; L3.2@57.486,5.062 58.411,5.987 58.411,8.665 59.496,9.75 R64.1@62.954,9.75 ; J3.98@61.35,61.919 61.35,63.793 pad.2@61.35,64.625 pad.2@61.35,65.45 ; J3.112@66.95,62.25 66.95,63.793 pad.2@66.95,64.625 pad.2@66.95,65.45 ; J13.1@83.759,72.04 J13.1@84,72.04 88.806,72.04 95.71,65.136 105.234,65.136 pad.2@105.391,65.293 ; J4.158@105.548,61.928 pad.2@105.548,64.625 105.548,65.136 pad.2@105.548,65.45 ; J4.180@114.348,61.928 pad.2@114.348,64.625 114.348,65.037
  Top Layer w1: pad.2@78.86,23.437 pad.2@79.506,23.437 109.824,23.437 113.379,26.993 113.379,35.198 117.429,39.248 117.429,64.012 116.403,65.037 114.348,65.037 105.646,65.037 105.548,65.136
  Bottom Layer w0.254: pad.2@48.478,7.174 49.634,7.174 51.518,5.29 pad.2@59.049,5.29
  Bottom Layer w0.5: J11.1@4,72.04 10.431,72.04 13.637,75.246 41.174,75.246 J12.1@44.38,72.04 ; pad.2@40.11,50.823 40.11,61.884 38.15,63.844 pad.2@38.15,64.625 pad.2@38.15,65.45 38.15,65.784 38.647,66.281 42.437,66.281 42.863,66.707 42.863,70.523 J12.1@44.38,72.04 ; pad.2@55.754,64.625 pad.2@55.754,65.45 54.572,65.45 47.982,72.04 J12.1@44.38,72.04 ; pad.2@59.03,5.309 pad.2@59.049,5.29
  Bottom Layer w1: 56.109,65.095 57.796,65.095 58.326,65.625 59.719,65.625 60.208,65.136 105.548,65.136 ; pad.2@61.63,5.034 pad.2@66.81,5.034 pad.2@69.396,5.034 70.32,5.034 71.827,3.526 75.134,3.526 76.876,5.268 76.876,10.874 75.322,12.427 75.322,20.424 78.335,23.437 pad.2@78.86,23.437 pad.2@79.506,23.437 pad.2@80.135,23.437
+12_48: C51.1 C52.1 D14.2 L2.2 pad.2@63.205,17.574 pad.2@63.205,18.357 pad.2@63.205,19.9 pad.2@63.205,19.111 pad.2@64.182,17.574 pad.2@64.182,18.357 R57.2 | length 3.2
  Bottom Layer w0.5: R57.2@61.573,13.361 61.573,14.135 62.161,14.722 62.161,16.229 C52.1@62.1,16.29
+12_Bat_Iso: C37.1 C38.1 C39.1 C40.1 D8.1 D10.2 pad.2@33.958,22.769 pad.2@35.75,30.56 pad.2@37.678,22.769 pad.2@41.428,22.769 pad.2@45.15,22.769 pad.2@48,22.769 R10.1 R46.2 R48.2 | length 41.8
  Top Layer w0.254: pad.2@35.75,30.56 35.75,22.935 C37.1@35.841,22.844
  Bottom Layer w0.254: pad.2@35.75,30.56 35.75,41.565 37.678,43.493 38.647,43.493 39.25,44.096 39.25,59.669 37.269,61.65 R10.1@37.269,61.775
+12V: C13.1 C14.1 C59.1 C64.1 C66.1 C68.1 C74.1 C75.1 D4.2 D5.2 D6.2 D10.1 D14.1 pad.2@21.127,38.767 pad.2@48.497,13.115 pad.2@48.626,5.003 pad.2@49.102,50.148 pad.2@49.194,11.4 pad.2@49.194,13.115 pad.2@49.495,5.003 pad.2@49.862,50.148 pad.2@50.917,33.714 pad.2@50.917,34.366 pad.2@68.103,22.294 pad.2@68.823,22.294 pad.2@72.991,18.435 U2.15 U2.17 U11.2 U11.9 U11.10 U12.3 U13.3 | length 171.3
  Top Layer w0.254: C74.1@49.699,10.489 49.799,10.489 49.972,10.316 49.972,9.843 50.325,9.49 50.325,9.023 U11.2@50.327,9.021 ; U2.17@53.726,47.023 53.749,47 U2.17@54.3,47 54.3,47.529 54.55,47.779 56.413,47.779 56.727,48.094 56.727,48.927 U2.15@56.75,48.95
  Top Layer w0.5: U13.3@19.477,37.573 U13.3@19.427,37.523 20.257,37.523 20.55,37.816 20.55,38.163 21.127,38.74 pad.2@21.127,38.767 C64.1@22.115,38.767 22.115,38.742 C64.1@21.89,38.517 ; pad.2@49.102,50.148 pad.2@49.862,50.148 ; D4.2@49.527,33.071 50.917,33.071 ; C14.1@49.859,51.304 49.862,51.302 pad.2@49.862,50.148 ; C13.1@52.106,49.892 50.489,49.892 50.253,50.128 49.881,50.128 pad.2@49.862,50.148 ; C13.1@52.331,49.642 52.687,49.642 54.55,47.779 ; D5.2@62.599,30.76 62.652,30.707 68.022,30.707 ; D6.2@67.107,32.45 67.124,32.434 67.124,31.606 68.022,30.707 ; pad.2@68.823,22.294 68.823,24.964 70.36,26.5 72.003,26.5 72.551,27.048 72.551,29.875 71.719,30.707 68.022,30.707 ; C68.1@72.957,15.747 73.032,15.822 73.032,16.563 72.232,17.363 U12.3@72.232,18.435 pad.2@72.991,18.435 pad.2@73.01,18.454
  Top Layer w1: pad.2@50.917,34.366 pad.2@50.917,33.714 50.917,33.071 50.917,32.368 48.626,30.077 48.626,28.432 50.48,26.578 66.415,26.578 68.255,24.738 68.255,22.447 pad.2@68.103,22.294 pad.2@68.823,22.294
  Bottom Layer w0.5: pad.2@21.127,38.767 22.756,38.767 33.523,28 46.333,28 47.369,29.036 47.369,31.515 49.568,33.714 pad.2@50.917,33.714 50.919,34.366 50.936,40.045 50.426,40.555 50.426,49.556 49.862,50.121 pad.2@49.862,50.148 pad.2@49.102,50.148 ; D10.1@67.014,22.294 pad.2@68.823,22.294 ; pad.2@68.103,22.294 68.103,19.21 68.878,18.435 pad.2@72.991,18.435
  Bottom Layer w1.2: 47.5,10 62.131,10 67.014,14.883 D14.1@67.014,19.5 D10.1@67.014,22.294
+12V_BAT: C41.1 D9.2 J16.5 J16.6 | length 17
  Top Layer w0.5: D9.2@17.173,2.519 17.325,2.519 18.375,3.569 18.375,4.323 18.896,4.844 C41.1@21.847,4.844
  Top Layer w1.8: J16.6@9.98,8.42 J16.5@12.52,8.42 13.431,8.42 16.773,5.078 16.773,2.919 D9.2@17.173,2.519
+12V_BAT_PROT: C33.1 C42.2 C43.2 C44.2 C47.1 D9.1 D11.1 D12.2 pad.2@20.902,16.631 pad.2@24.282,16.631 pad.2@27.662,16.631 pad.2@30.966,16.631 pad.2@33.249,4.346 pad.2@33.249,14.293 R47.2 R48.1 R49.2 T1.1 T1.2 U8.1 U9.3 | length 85.1
  Top Layer w0.5: pad.2@33.249,4.346 37.092,4.346 38.146,5.4 41.11,5.4 44.796,1.714 75.195,1.714 78.793,5.312 81.319,5.312 84.08,2.55 88.579,2.55 90.974,4.945 C33.1@91.224,4.945 91.474,4.945 91.774,4.645 91.774,4.553 92.317,4.009 U8.1@93.567,4.009
  Top Layer w1.8: D9.1@17.332,9.719 D11.1@17.332,14.228
  Bottom Layer w0.5: R49.2@23.659,14.459 23.659,15.982 24.282,16.604 pad.2@24.282,16.631 ; R47.2@32.511,11.141 33.699,11.141 33.848,10.992 ; pad.2@33.249,4.346 33.848,4.944 33.848,10.992 ; pad.2@33.249,14.293 33.848,13.694 33.848,10.992
+48V: C3.2 C57.1 C58.1 J18.2 J18.3 pad.2@31.287,49.804 pad.2@39.922,42.825 pad.2@43.662,42.825 pad.2@44.458,42.825 pad.2@51.055,19.889 pad.2@51.868,19.889 pad.2@52.681,19.889 R38.1 U2.23 U10.2 U10.3 | length 55.4
  Top Layer w0.254: pad.2@31.287,49.804 34.794,46.297 34.794,43.956 35.909,42.841 pad.2@39.835,42.841 ; C3.2@44.469,44.254 49.212,44.254 49.213,44.256 53.042,44.256 53.298,44 U2.23@54.3,44
  Top Layer w1: pad.2@43.643,42.825 C3.2@43.643,44.244 ; pad.2@43.662,42.825 pad.2@44.458,42.825 44.458,44.244 C3.2@44.469,44.254
  Bottom Layer w0.254: R38.1@25.128,51.444 25.128,50.103 26.554,48.677 30.16,48.677 pad.2@31.287,49.804 ; pad.2@39.922,42.825 pad.2@43.662,42.825
  Bottom Layer w1: J18.2@41.29,29.599 J18.3@43.83,29.599 43.83,29.694 44.068,29.933 44.068,42.817 44.06,42.825 ; pad.2@43.662,42.825 44.06,42.825 ; pad.2@44.458,42.825 44.06,42.825
AMR_COS_N: C94.2 J3.33 pad.2@32.55,55.875 R85.2 R86.2 | length 9.5
  Top Layer w0.254: pad.2@32.55,55.875 J3.33@32.55,58.519
  Bottom Layer w0.254: pad.2@32.55,55.875 32.55,54.278 32.945,53.882 R85.2@32.945,52.985 ; C94.2@36.675,52.985 C94.2@36.75,53.06
  Bottom Layer w0.5: R85.2@32.945,52.985 34.809,52.985 C94.2@36.675,52.985
AMR_COS_P: C89.2 J3.31 pad.2@31.75,55.875 R79.2 R82.2 | length 9.6
  Top Layer w0.254: pad.2@31.75,55.875 J3.31@31.75,58.519
  Bottom Layer w0.254: C89.2@27.481,53.06 C89.2@27.556,52.985 ; R79.2@31.287,52.985 31.287,53.898 31.75,54.361 pad.2@31.75,55.875
  Bottom Layer w0.5: C89.2@27.556,52.985 R79.2@31.287,52.985
AMR_COSN_IN: J17.8 R85.1 | length 32.8
  Bottom Layer w0.254: J17.8@9.98,42.12 11.293,42.12 11.368,42.046 11.426,41.987 ccw(c12.52,42.12) 13.299,41.341 13.624,41.666 31.487,41.666 32.377,42.556 32.377,50.967 32.622,51.212 32.622,51.337 32.82,51.535 R85.1@32.945,51.535
AMR_COSP_IN: J17.7 R79.1 | length 28.8
  Bottom Layer w0.254: J17.7@12.52,42.12 31.299,42.12 31.923,42.744 31.923,50.899 31.61,51.212 31.61,51.337 31.412,51.535 R79.1@31.287,51.535
AMR_SIN_N: C86.2 J3.27 R77.2 R78.2 | length 9.6
  Top Layer w0.254: J3.27@30.15,58.519 30.15,54.342 30.533,53.959 R77.2@30.533,52.989 ; R77.2@30.611,52.989 30.591,52.969 32.455,52.969 34.322,52.969 C86.2@34.397,53.044
AMR_SIN_P: C85.2 J3.25 R74.2 R76.2 | length 9.6
  Top Layer w0.254: C85.2@25.128,53.044 C85.2@25.203,52.969 ; R74.2@28.932,52.969 28.932,53.94 29.35,54.357 J3.25@29.35,58.519
  Top Layer w0.5: C85.2@25.203,52.969 R74.2@28.932,52.969
AMR_SINN_IN: J17.6 R77.1 | length 36.2
  Top Layer w0.254: J17.6@9.98,39.58 10.154,39.406 11.283,39.406 11.432,39.257 11.57,39.022 ccw(c12.52,39.58) 13.474,39.029 13.571,39.126 14.834,39.126 15.358,38.602 20.085,38.602 20.5,39.017 20.5,39.027 22.019,40.546 31.673,40.546 32.443,41.317 32.443,47.268 29.896,49.816 29.896,51.134 30.099,51.337 30.393,51.337 R77.1@30.591,51.535
AMR_SINP_IN: J17.5 R74.1 | length 32.1
  Top Layer w0.254: J17.5@12.52,39.58 15.022,39.58 15.546,39.056 19.897,39.056 20.046,39.205 20.046,39.215 21.831,41 31.485,41 31.989,41.505 31.989,47.08 29.442,49.628 29.442,51.188 29.293,51.337 29.13,51.337 R74.1@28.932,51.535
CAN_EN: pad.2@90.999,13.918 R44.2 U6.8 U7.14 | length 13.3
  Top Layer w0.254: U7.14@89.816,13.918 pad.2@90.999,13.918 91.565,14.484 96.302,14.484 96.451,14.336 U6.8@96.451,13.777
  Bottom Layer w0.254: R44.2@86.266,16.558 87.246,16.558 89.887,13.918 pad.2@90.999,13.918
CAN_EN_MCU: J3.92 pad.2@58.95,64.625 pad.2@78.75,13.918 R44.1 U7.3 | length 128.8
  Top Layer w0.254: J3.92@58.95,61.919 pad.2@58.95,64.625 ; pad.2@78.75,13.918 U7.3@80.066,13.918
  Bottom Layer w0.254: pad.2@58.95,64.625 58.95,61.05 59.296,60.704 69.592,60.704 75.077,55.219 103.63,55.219 103.849,55 107.668,51.181 107.668,39.287 101.709,33.328 101.709,26.325 98.459,23.076 83.613,23.076 77.057,16.52 77.057,13.148 77.206,12.999 77.917,12.999 78.193,13.275 78.601,13.275 78.75,13.424 pad.2@78.75,13.918 80.526,13.918 83.167,16.558 R44.1@84.234,16.558
CAN_H: C29.1 D7.2 J15.7 J16.2 L1.1 pad.2@103.405,2.646 R34.2 R35.2 | length 132.2
  Top Layer w0.5: pad.2@103.405,2.646 103.405,5.924 D7.2@103.405,5.964 103.405,8.176 103.33,8.251 R34.2@103.33,9.75 ; L1.1@104.78,11.54 103.661,11.54 103.305,11.183 103.305,9.775 103.317,9.763 R34.2@103.33,9.75 ; J15.7@117.366,17.749 114.243,17.749 113.95,17.456 113.95,14.719 113.392,14.161 113.392,10.372 112.649,9.628 112.021,9.628 112.01,9.617 110.739,9.617 109.422,8.3 R35.2@107.556,8.3 105.929,8.3 104.479,9.75 R34.2@103.33,9.75
  Bottom Layer w0.5: J16.2@9.98,3.34 11.25,2.07 13.619,2.07 14.189,2.64 35.801,2.64 38.581,5.419 41.091,5.419 45.094,1.416 75.358,1.416 79.051,5.109 81.046,5.109 83.605,2.55 102.937,2.55 103.014,2.627 103.386,2.627 pad.2@103.405,2.646
CAN_L: C31.2 D7.1 J15.2 J16.1 L1.2 pad.2@105.305,6.864 pad.2@105.305,13.127 R36.1 R37.2 | length 129.9
  Top Layer w0.5: L1.2@104.78,14.04 104.778,14.038 103.598,14.038 103.305,14.331 103.305,15.804 103.33,15.829 104.729,15.829 105.798,16.899 R36.1@107.556,16.899 109.046,16.899 110.996,14.949 111.945,14.949 C31.2@111.958,14.961 111.973,14.946 112.89,14.946 113.25,15.307 113.25,17.86 114.524,19.134 J15.2@117.366,19.134 ; L1.2@105.086,13.84 105.205,13.84 105.205,13.721 105.286,13.64 105.286,13.146 pad.2@105.305,13.127 ; D7.1@105.305,5.964 pad.2@105.305,6.864
  Bottom Layer w0.5: J16.1@12.52,3.34 35.512,3.34 38.291,6.119 41.381,6.119 45.384,2.116 75.068,2.116 78.761,5.809 81.336,5.809 83.895,3.25 102.647,3.25 105.305,5.908 pad.2@105.305,6.864 pad.2@105.305,13.127
CAN_RX_XCVR: pad.2@90.999,11.378 R42.2 U6.4 U7.12 | length 9
  Top Layer w0.254: U7.12@89.816,11.378 92.075,11.378 92.524,11.827 U6.4@93.851,11.827
  Bottom Layer w0.254: R42.2@86.266,11.378 pad.2@90.999,11.378
CAN_TX_XCVR: pad.2@90.999,12.648 R43.2 U6.1 U7.13 | length 9.8
  Top Layer w0.254: U7.13@89.816,12.648 pad.2@90.999,12.648 91.067,12.648 92.215,13.795 93.832,13.795 U6.1@93.851,13.777
  Bottom Layer w0.254: R43.2@86.266,13.968 88.426,13.968 89.746,12.648 pad.2@90.999,12.648
CANB_RX/CANA_TX: J3.95
CANB_TX/CANA_RX: J3.94
DACA_MMCX: J3.9 R1.2 | length 9.4
  Top Layer w0.5: R1.2@17.782,54.667 21.127,54.667 21.61,54.184 22.395,54.184 22.95,54.739 J3.9@22.95,58.519
DACB_MMCX: J3.11 R4.2 | length 10.7
  Top Layer w0.5: R4.2@17.782,52.725 21.926,52.725 23.75,54.549 J3.11@23.75,58.519
DHA: R16.1 U2.28 | length 6.6
  Top Layer w0.254: R16.1@48.583,39.558 R16.1@48.566,39.541 50.325,41.3 53.248,41.3 53.448,41.5 U2.28@54.3,41.5 U2.28@54.277,41.477
DHB: pad.2@59.25,38.692 R17.1 U2.39 | length 7.9
  Top Layer w0.254: U2.39@59.25,37.55 pad.2@59.25,38.692
  Bottom Layer w0.254: R17.1@54.566,34.066 54.566,34.374 58.817,38.626 59.184,38.626 pad.2@59.25,38.692
DHC: pad.2@65.708,38.975 R18.1 U2.49 | length 4.2
  Top Layer w0.254: U2.49@65.7,39.5 65.708,39.492 pad.2@65.708,38.975
  Bottom Layer w0.254: pad.2@65.708,38.975 66.292,38.392 R18.1@69.096,38.392
DRV_ASCSEL: J3.61 pad.2@46.95,55.875 pad.2@60.25,47.811 U2.8 | length 23.2
  Top Layer w0.254: pad.2@46.95,55.875 J3.61@46.95,58.519 ; U2.8@60.227,48.973 U2.8@60.25,48.95 pad.2@60.25,47.811
  Bottom Layer w0.254: pad.2@46.95,55.875 46.95,55.071 49.121,52.9 51.998,52.9 52.353,52.545 58.862,52.545 59.123,52.283 59.123,50.625 59.49,50.257 60.101,50.257 60.25,50.109 pad.2@60.25,47.811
